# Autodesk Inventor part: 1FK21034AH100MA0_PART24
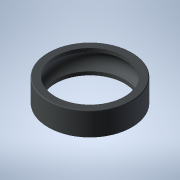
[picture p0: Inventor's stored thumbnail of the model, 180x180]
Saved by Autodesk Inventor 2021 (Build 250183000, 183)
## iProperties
Created: 2025-04
Part Number: 1FK21034AH100MA0_PART24
Material: Generic
Catalog Web Link: www.3dfindit.com
Description: -Servo synchronous motor
Document SubType Name: Modeling
Designer: psAdmin
Mass: 1.46378 g
Surface Area: 23.3636 cm^2
Volume: 1.46378 cm^3
Density: 1 g/cm^3
Appearance: PSOLRGB-212-217-219
Category: PARTsolutions
Title: 1FK21034AH100MA0_PART24
Author: Cadenas PARTsolutions
Comments: Servo synchronous motor
Sending System: PARTsolutions
Preprocessor: ST-DEVELOPER v19.3
PSOL_IDENT_0: {$CADENAS_DATA/23d-libs/siemens_ag/_cat_/39/97/1fk21034ah100ma0.prj},216 {VTYP=3D},{NB=1FK21034AH100
PSOL_IDENT_1: MA0_PART24},{LINA=1FK21034AH100MA0_PART24},{NN=1FK21034AH100MA0_PART24},{NOPRJ=TRUE},{DATE=19.08.202
PSOL_IDENT_2: 5 14:00:33},{GEOMDATE=30.07.2025 02:02:21},{VERSION=},{LINEID=10},{WBVAR=},{WBNUMERIC=}  {NB=1FK2103
PSOL_IDENT_3: 4AH100MA0_PART24},{LINA=1FK21034AH100MA0_PART24},{KT=DUMMY},{PREVIEW=../../../_pool_/d3/78/p_d211_xx
PSOL_IDENT_4: _00934j.png},{DESCSHORT=SIMOTICS S-1FK2 HD, SINAMICS S210 3AC 400V-480V, 1.01 Nm, 4500 rpm},{DESCLON
PSOL_IDENT_5: G=SIMOTICS S-1FK2 HD servo motor M0=1.27 Nm; PN = 0.48 kW at nN=4500 rpm (380-480 V); PN = 0.3 kW at
PSOL_IDENT_6: nN=2500 rpm (200-240 V); with holding brake; degree of protection IP64; cylindrical shaft D14 x 30
PSOL_IDENT_7: mm; absolute encoder 22-bit + 12-bit multiturn (encoder AM22DQC); with OCC interface; plug size M17,
PSOL_IDENT_8: rotatable; SIMOTICS S-1FK2 servomotorfor a wide range of uses in industrial environments. SIMOTICS
PSOL_IDENT_9: S‑1FK2 servomotors are compact synchronous motors with a high dynamic performance that set themselve
PSOL_IDENT_10: s apart as a result of their high power density, degree of protection and overload capability. The m
PSOL_IDENT_11: otors are available in two variants: as High Dynamic variant (highest dynamic performance as a resul
PSOL_IDENT_12: t of the low intrinsic moment of inertia for applications demanding a high dynamic performance with
PSOL_IDENT_13: low moved masses) - and as Compact variant (precise and stable closed-loop control for medium up to
PSOL_IDENT_14: large moved masses as a result of a medium intrinsic moment of inertia). SIMOTICSS‑1FK2 servomotors
PSOL_IDENT_15: fully exploit their strengths in a system with the SINAMICSS210 frequency converter and simple conne
PSOL_IDENT_16: ction using the one cable connection (OCC). Advantages include the short control and positioning tim
PSOL_IDENT_17: es, fast and precise correction of disturbing quantities as well as stable control with a high dynam
PSOL_IDENT_18: ic performance. The servo motors can be configured to address a wide range of requirements. For exam
PSOL_IDENT_19: ple with and without holding brake, IP64 or IP65 degree of protection, singleturn or multiturn absol
PSOL_IDENT_20: ute encoders - to name just a few. Further, the servomotors are available in different shaft heights
PSOL_IDENT_21: extending from 20 to 100. A shaft sealing ring is available to achieve an IP65 degree of protection
PSOL_IDENT_22: and for subsequent mounting at the motor or as spare part. SIMOTICS - the optimum motor for each an
PSOL_IDENT_23: d every motion control application.},{INTNO=195125454019},{SUPPLIERALTNO=1FK2103-4AH10-0MA0},{MANUID=
PSOL_IDENT_24: 1FK21034AH100MA0},{MANUNAME=Siemens},{MANUTYPEDESC=SYNCHRONOUS MOTOR 1FK2 HD 1,27 NM},{AAU732=SIMOTI
PSOL_IDENT_25: CS},{AAO057=S-1FK2},{AAU734=SIMOTICS S-1FK2 HD servo motor M0=1.27 Nm; PN = 0.48 kW at nN=4500 rpm (
PSOL_IDENT_26: 380-480 V); PN = 0.3 kW at nN=2500 rpm (200-240 V); with holding brake; degree of protection IP64; c
PSOL_IDENT_27: ylindrical shaft D14 x 30 mm; absolute encoder 22-bit + 12-bit multiturn (encoder AM22DQC); with OCC
PSOL_IDENT_28: interface; plug size M17, rotatable;},{AAW338=SYNCHRONOUS MOTOR 1FK2 HD 1,27 NM},{AAO742=SIMOTICS},
PSOL_IDENT_29: {AAO663=4034106444921},{NOCUPEROU=1},{PRICEQUANTITY=1},{QUANTITYMIN=1},{QUANTITYINT=1},{CTN=85015100
PSOL_IDENT_30: },{COO=RO},{AAO676=1FK2103-4AH10-0MA0},{AAO677=Siemens AG},{ORDERUNIT=C62},{CONTENTUNIT=C62}
NB: 1FK21034AH100MA0_PART24
NT: Servo synchronous motor
NBSYN: $MANUID._PART24
LINA: 1FK21034AH100MA0_PART24
CATALOG: SIEMENS
PREVIEW: ../../../_pool_/d3/78/p_d211_xx_00934j.png
DESCSHORT: SIMOTICS S-1FK2 HD, SINAMICS S210 3AC 400V-480V, 1.01 Nm, 4500 rpm
DESCLONG: SIMOTICS S-1FK2 HD servo motor M0=1.27 Nm; PN = 0.48 kW at nN=4500 rpm (380-480 V); PN = 0.3 kW at nN=2500 rpm (200-240 V); with holding brake; degree of protec
INTNO: 195125454019
SUPPLIERALTNO: 1FK2103-4AH10-0MA0
MANUID: 1FK21034AH100MA0
MANUNAME: Siemens
MANUTYPEDESC: SYNCHRONOUS MOTOR 1FK2 HD 1,27 NM
AAU732: SIMOTICS
AAO057: S-1FK2
AAU734: SIMOTICS S-1FK2 HD servo motor M0=1.27 Nm; PN = 0.48 kW at nN=4500 rpm (380-480 V); PN = 0.3 kW at nN=2500 rpm (200-240 V); with holding brake; degree of protec
AAW338: SYNCHRONOUS MOTOR 1FK2 HD 1,27 NM
AAO742: SIMOTICS
AAO663: 4034106444921.0
NOCUPEROU: 1
PRICEQUANTITY: 1
QUANTITYMIN: 1
QUANTITYINT: 1
CTN: 85015100
COO: RO
ARTICLENO: 1FK21034AH100MA0_PART24
BOMINFO: 1FK21034AH100MA0_PART24
CREATOR: CADENAS GmbH
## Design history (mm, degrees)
feature "2025_04_17_15_09_00_0361"
body "Solid1"
